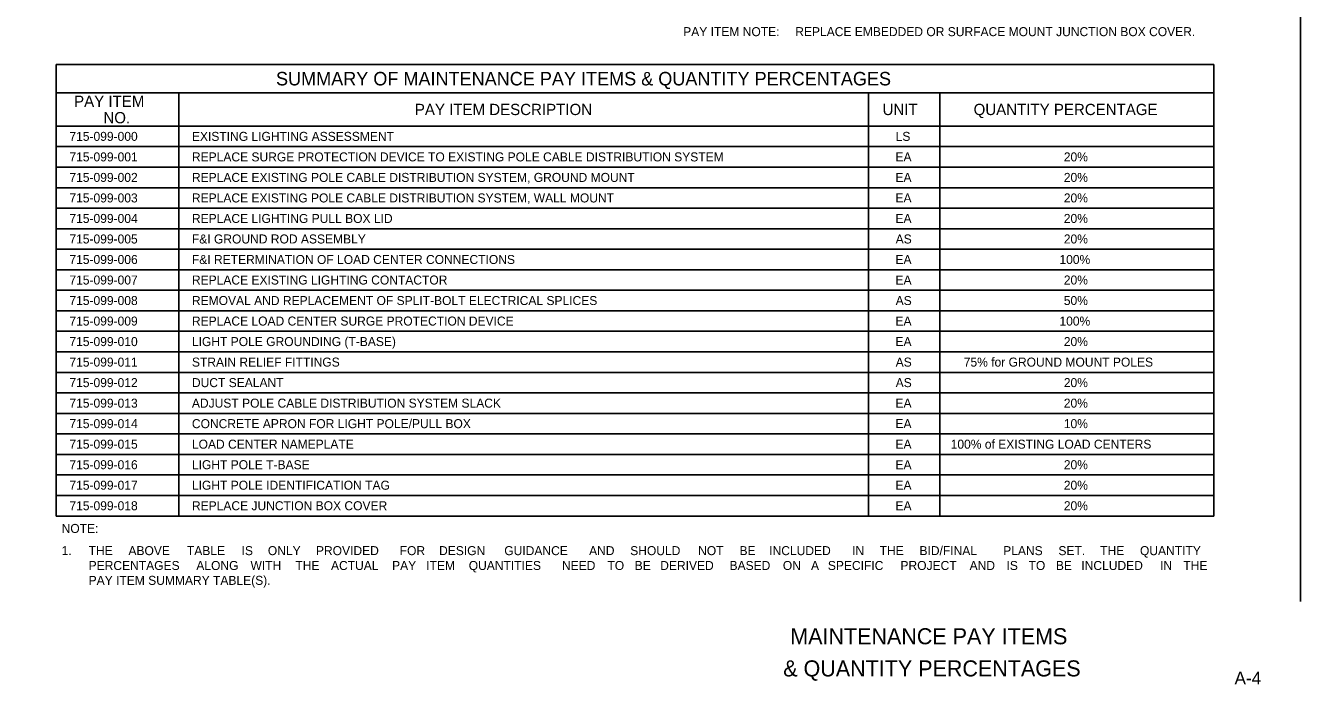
# Model space of a CAD drawing. Extents: x -55 to 2471539, y -90 to 3608906.
# Drawn here: x 549 to 1540, y -64 to 448 of the extents above; entities that cross this region are included whole.
import ezdxf

# ---------------------------------------------------------------- set-up
doc = ezdxf.new("R2010")
doc.units = 0
for name, color, linetype in [('NonPlottingEle_dp', 7, 'Continuous'), ('SumBoxBorder_dp', 7, 'Continuous'), ('SumBoxLines_dp', 7, 'Continuous'), ('SumBoxLinesMin_dp', 7, 'Continuous'), ('TextLabel', 7, 'Continuous'), ('TextMisc', 7, 'Continuous'), ('TextNotes', 7, 'Continuous'), ('TextShtNo', 7, 'Continuous')]:
    doc.layers.add(name, color=color, linetype=linetype)

msp = doc.modelspace()

# ---------------------------------------------------------------- linework, layer by layer
at = {"layer": 'NonPlottingEle_dp'}
msp.add_lwpolyline([(0, 0), (0, 960), (1540, 960), (1540, 0)], dxfattribs=at)
at = {"layer": 'SumBoxBorder_dp'}
for p, q in [((572.5, 417.37), (1472.5, 417.37)), ((572.5, 417.37), (572.5, 66.47)), ((1472.5, 417.37), (1472.5, 66.47)), ((572.5, 369.52), (1472.5, 369.52)), ((572.5, 369.52), (1472.5, 369.52)), ((572.5, 66.47), (1472.5, 66.47))]:
    msp.add_line(p, q, dxfattribs=at)
at = {"layer": 'SumBoxLines_dp'}
for p, q in [((572.5, 395.42), (1472.5, 395.42)), ((572.5, 395.42), (1472.5, 395.42)), ((667.75, 395.42), (667.75, 66.47)), ((667.75, 395.42), (667.75, 66.47)), ((1204, 395.42), (1204, 66.47)), ((1204, 395.42), (1204, 66.47)), ((1259.5, 395.42), (1259.5, 66.47)), ((1259.5, 395.42), (1259.5, 66.47)), ((572.5, 353.57), (1472.5, 353.57)), ((580.75, 353.57), (1204, 353.57))]:
    msp.add_line(p, q, dxfattribs=at)
at = {"layer": 'SumBoxLinesMin_dp'}
for p, q in [((1204, 353.57), (1259.5, 353.57)), ((572.5, 337.62), (1259.5, 337.62)), ((572.5, 337.62), (1472.5, 337.62)), ((572.5, 321.67), (1472.5, 321.67)), ((572.5, 321.67), (1472.5, 321.67)), ((572.5, 305.72), (1472.5, 305.72)), ((572.5, 305.72), (1472.5, 305.72)), ((572.5, 289.77), (1472.5, 289.77)), ((572.5, 289.77), (1472.5, 289.77)), ((572.5, 273.82), (1472.5, 273.82)), ((572.5, 273.82), (1472.5, 273.82)), ((572.5, 257.87), (1472.5, 257.87)), ((572.5, 257.87), (1472.5, 257.87)), ((572.5, 241.92), (1472.5, 241.92)), ((572.5, 241.92), (1472.5, 241.92)), ((572.5, 225.97), (1472.5, 225.97)), ((572.5, 225.97), (1472.5, 225.97)), ((572.5, 210.02), (1472.5, 210.02)), ((572.5, 210.02), (1472.5, 210.02)), ((572.5, 194.07), (1472.5, 194.07)), ((572.5, 194.07), (1472.5, 194.07)), ((572.5, 178.12), (1472.5, 178.12)), ((572.5, 178.12), (1472.5, 178.12)), ((572.5, 162.17), (1472.5, 162.17)), ((572.5, 162.17), (1472.5, 162.17)), ((572.5, 146.22), (1472.5, 146.22)), ((572.5, 146.22), (1472.5, 146.22)), ((572.5, 130.27), (1472.5, 130.27)), ((572.5, 130.27), (1472.5, 130.27)), ((572.5, 114.32), (1472.5, 114.32)), ((580.75, 114.32), (667.75, 114.32)), ((676, 114.32), (1472.5, 114.32)), ((572.5, 98.37), (1472.5, 98.37)), ((580.75, 98.37), (667.75, 98.37)), ((1259.5, 98.37), (1472.5, 98.37)), ((572.5, 82.42), (1472.5, 82.42)), ((580.75, 82.42), (667.75, 82.42)), ((1259.5, 82.42), (1472.5, 82.42))]:
    msp.add_line(p, q, dxfattribs=at)

# ---------------------------------------------------------------- texts
at = {"layer": 'TextLabel'}
for s, height, p in [('SUMMARY OF MAINTENANCE PAY ITEMS & QUANTITY PERCENTAGES', 10.5, (743.38, 401.15)), ('PAY ITEM', 8.75, (586.39, 384.47)), ('PAY ITEM DESCRIPTION', 8.75, (851.34, 378.1)), ('UNIT', 8.75, (1215.03, 378.1)), ('QUANTITY PERCENTAGE', 8.75, (1285.82, 378.1)), ('NO.', 8.75, (609.17, 371.72)), ('715-099-000', 7, (582.75, 358.05)), ('EXISTING LIGHTING ASSESSMENT', 7, (678, 358.05)), ('LS', 7, (1225.22, 358.05)), ('715-099-001', 7, (582.75, 342.1)), ('REPLACE SURGE PROTECTION DEVICE TO EXISTING POLE CABLE DISTRIBUTION SYSTEM', 7, (678, 342.1)), ('EA', 7, (1225.07, 342.1)), ('20%', 7, (1355.97, 342.1)), ('715-099-002', 7, (582.75, 326.15)), ('REPLACE EXISTING POLE CABLE DISTRIBUTION SYSTEM, GROUND MOUNT', 7, (678, 326.15)), ('EA', 7, (1225.07, 326.15)), ('20%', 7, (1355.97, 326.15)), ('715-099-003', 7, (582.75, 310.2)), ('REPLACE EXISTING POLE CABLE DISTRIBUTION SYSTEM, WALL MOUNT', 7, (678, 310.2)), ('20%', 7, (1355.97, 310.2)), ('EA', 7, (1225.07, 310.2)), ('715-099-004', 7, (582.75, 294.25)), ('REPLACE LIGHTING PULL BOX LID', 7, (678, 294.25)), ('EA', 7, (1225.07, 294.25)), ('20%', 7, (1355.97, 294.25)), ('715-099-005', 7, (582.75, 278.3)), ('F&I GROUND ROD ASSEMBLY', 7, (678, 278.3)), ('AS', 7, (1225.22, 278.3)), ('20%', 7, (1355.97, 278.3)), ('715-099-006', 7, (582.75, 262.35)), ('F&I RETERMINATION OF LOAD CENTER CONNECTIONS', 7, (678, 262.35)), ('EA', 7, (1225.07, 262.35)), ('100%', 7, (1352.58, 262.35)), ('715-099-007', 7, (582.75, 246.4)), ('REPLACE EXISTING LIGHTING CONTACTOR', 7, (678, 246.4)), ('EA', 7, (1225.07, 246.4)), ('20%', 7, (1355.97, 246.4)), ('715-099-008', 7, (582.75, 230.45)), ('REMOVAL AND REPLACEMENT OF SPLIT-BOLT ELECTRICAL SPLICES', 7, (678, 230.45)), ('AS', 7, (1225.22, 230.45)), ('50%', 7, (1355.97, 230.45)), ('715-099-009', 7, (582.75, 214.5)), ('REPLACE LOAD CENTER SURGE PROTECTION DEVICE', 7, (678, 214.5)), ('EA', 7, (1225.07, 214.5)), ('100%', 7, (1352.58, 214.5)), ('715-099-010', 7, (582.75, 198.55)), ('LIGHT POLE GROUNDING (T-BASE)', 7, (678, 198.55)), ('EA', 7, (1225.07, 198.55)), ('20%', 7, (1355.97, 198.55)), ('715-099-011', 7, (582.75, 182.6)), ('STRAIN RELIEF FITTINGS', 7, (678, 182.6)), ('AS', 7, (1225.22, 182.6)), ('75% for GROUND MOUNT POLES', 7, (1278.16, 182.6)), ('715-099-012', 7, (582.75, 166.65)), ('DUCT SEALANT', 7, (678, 166.65)), ('AS', 7, (1225.22, 166.65)), ('20%', 7, (1355.97, 166.65)), ('715-099-013', 7, (582.75, 150.7)), ('ADJUST POLE CABLE DISTRIBUTION SYSTEM SLACK', 7, (678, 150.7)), ('EA', 7, (1225.07, 150.7)), ('20%', 7, (1355.97, 150.7)), ('715-099-014', 7, (582.75, 134.75)), ('CONCRETE APRON FOR LIGHT POLE/PULL BOX', 7, (678, 134.75)), ('EA', 7, (1225.07, 134.75)), ('10%', 7, (1355.97, 134.75)), ('715-099-015', 7, (582.75, 118.8)), ('LOAD CENTER NAMEPLATE', 7, (678, 118.8)), ('EA', 7, (1225.07, 118.8)), ('100% of EXISTING LOAD CENTERS', 7, (1268, 118.8)), ('715-099-016', 7, (582.75, 102.85)), ('LIGHT POLE T-BASE', 7, (678, 102.85)), ('EA', 7, (1225.07, 102.85)), ('20%', 7, (1355.97, 102.85)), ('715-099-017', 7, (582.75, 86.9)), ('LIGHT POLE IDENTIFICATION TAG', 7, (678, 86.9)), ('EA', 7, (1225.07, 86.9)), ('20%', 7, (1355.97, 86.9)), ('715-099-018', 7, (582.75, 70.95)), ('REPLACE JUNCTION BOX COVER', 7, (678, 70.95)), ('EA', 7, (1225.07, 70.95)), ('20%', 7, (1355.97, 70.95)), ('NOTE:', 7, (576.69, 53.3)), ('1.', 7, (576.69, 36.05)), ('THE ', 7, (597.69, 36.05)), ('ABOVE ', 7, (628.64, 36.05)), ('TABLE ', 7, (674.11, 36.05)), ('IS ', 7, (716.61, 36.05)), ('ONLY ', 7, (737.05, 36.05)), ('PROVIDED ', 7, (774.45, 36.05)), ('FOR ', 7, (839.57, 36.05)), ('DESIGN ', 7, (870.18, 36.05)), ('GUIDANCE ', 7, (920.88, 36.05)), ('AND ', 7, (986.82, 36.05)), ('SHOULD ', 7, (1018.8, 36.05)), ('NOT ', 7, (1071.62, 36.05)), ('BE ', 7, (1103.8, 36.05)), ('INCLUDED ', 7, (1126.9, 36.05)), ('IN ', 7, (1191.39, 36.05)), ('THE ', 7, (1212.78, 36.05)), ('BID/FINAL ', 7, (1243.73, 36.05)), ('PLANS ', 7, (1308.82, 36.05)), ('SET. ', 7, (1351.76, 36.05)), ('THE ', 7, (1384.24, 36.05)), ('QUANTITY ', 7, (1415.19, 36.05)), ('PERCENTAGES ', 7, (597.69, 24.5)), ('ALONG ', 7, (681.43, 24.5)), ('WITH ', 7, (723.56, 24.5)), ('THE ', 7, (758.47, 24.5)), ('ACTUAL ', 7, (786.15, 24.5)), ('PAY ', 7, (833.66, 24.5)), ('ITEM ', 7, (860.21, 24.5)), ('QUANTITIES ', 7, (893.24, 24.5)), ('NEED ', 7, (965.73, 24.5)), ('TO ', 7, (1001.11, 24.5)), ('BE ', 7, (1022.31, 24.5)), ('DERIVED ', 7, (1042.13, 24.5)), ('BASED ', 7, (1096.03, 24.5)), ('ON ', 7, (1137.49, 24.5)), ('A ', 7, (1159.4, 24.5)), ('SPECIFIC ', 7, (1172.49, 24.5)), ('PROJECT ', 7, (1228.94, 24.5)), ('AND ', 7, (1282.7, 24.5)), ('IS ', 7, (1311.41, 24.5)), ('TO ', 7, (1328.57, 24.5)), ('BE ', 7, (1349.78, 24.5)), ('INCLUDED ', 7, (1369.6, 24.5)), ('IN ', 7, (1430.81, 24.5)), ('THE ', 7, (1448.92, 24.5)), ('PAY ITEM SUMMARY TABLE(S).', 7, (597.69, 12.95))]:
    msp.add_text(s, height=height, dxfattribs=at).set_placement(p)
at = {"layer": 'TextMisc'}
for s, p in [('MAINTENANCE PAY ITEMS', (1143.25, -33.24)), ('& QUANTITY PERCENTAGES', (1137.8, -58.24))]:
    msp.add_text(s, height=12.5, dxfattribs=at).set_placement(p)
at = {"layer": 'TextNotes'}
for s, p in [('PAY ITEM NOTE: ', (1060, 439.45)), ('REPLACE EMBEDDED OR SURFACE MOUNT JUNCTION BOX COVER.', (1147.13, 439.45))]:
    msp.add_text(s, height=7, dxfattribs=at).set_placement(p)
at = {"layer": 'TextShtNo'}
msp.add_text(' A-4 ', height=10, dxfattribs=at).set_placement((1484.99, -64.49))

doc.saveas('drawing.dxf')
